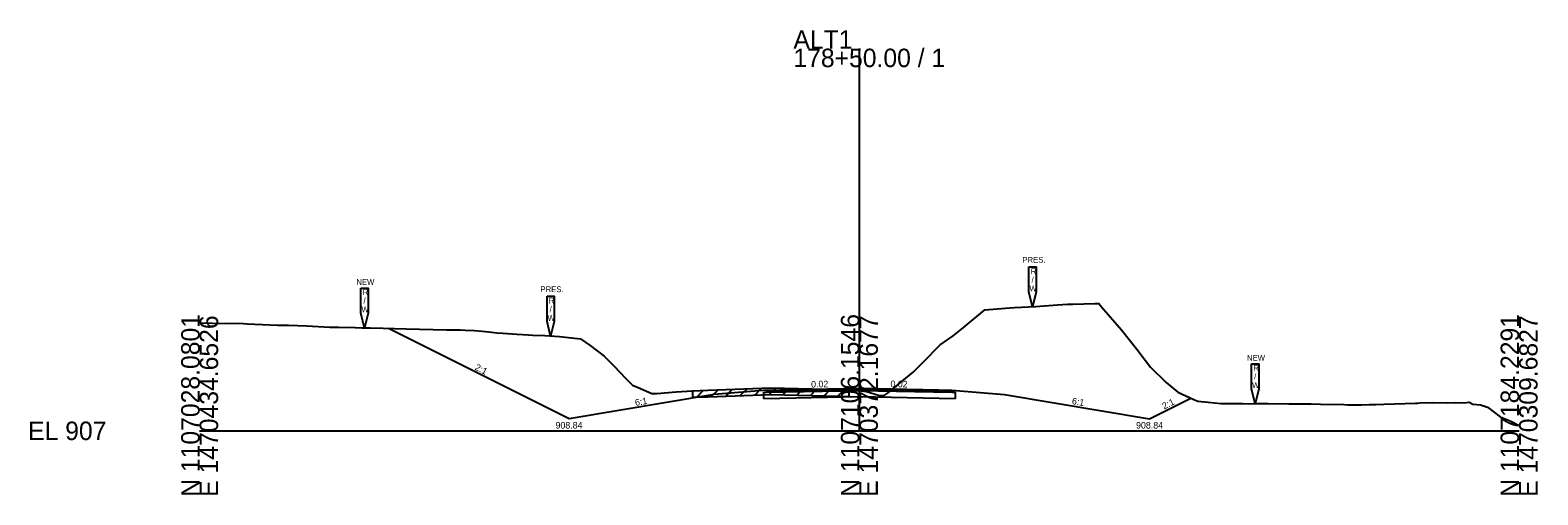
# Model space of a CAD drawing. Extents: x -26 to 2203, y -10 to 19568.
# Drawn here: x 1974.3 to 2202.8, y 490.3 to 560.7 of the extents above; entities that cross this region are included whole.
import ezdxf

# ---------------------------------------------------------------- set-up
doc = ezdxf.new("R2010")
doc.units = 0
for name, color, linetype in [('RD_GPK_XS_Cell', 7, 'Continuous'), ('RD_XS_Base', 7, 'Continuous'), ('RD_XS_ExGround', 7, 'Continuous'), ('RD_XS_ExPaveRet', 7, 'Continuous'), ('RD_XS_ExRW', 7, 'Continuous'), ('RD_XS_Greenside', 7, 'Continuous'), ('RD_XS_NewRW', 7, 'Continuous'), ('RD_XS_Pave', 7, 'Continuous'), ('RD_XS_TieSlope', 7, 'Continuous'), ('RD_XS_TX_Slope', 7, 'Continuous')]:
    doc.layers.add(name, color=color, linetype=linetype)

msp = doc.modelspace()

# ---------------------------------------------------------------- linework, layer by layer
at = {"layer": 'RD_GPK_XS_Cell'}
for p, q in [((2100, 500), (2100, 557.88)), ((2000, 500), (2100, 500)), ((2100, 500), (2200, 500))]:
    msp.add_line(p, q, dxfattribs=at)
at = {"layer": 'RD_XS_Base'}
for points in [[(2085.5, 505.84), (2086, 505.85), (2100, 506.13), (2114, 505.85), (2114.5, 505.84)], [(2085.5, 504.84), (2085.5, 505.84)], [(2114.5, 504.84), (2100, 505.13), (2085.5, 504.84)], [(2114.5, 505.84), (2114.5, 504.84)]]:
    msp.add_lwpolyline(points, dxfattribs=at)
at = {"layer": 'RD_XS_ExGround'}
msp.add_lwpolyline([(2000, 516.34), (2001.94, 516.31), (2006.64, 516.24), (2007.19, 516.22), (2011.84, 516.02), (2013.47, 515.98), (2016.25, 515.91), (2019.75, 515.7), (2021.05, 515.69), (2023.59, 515.65), (2024.6, 515.62), (2025.85, 515.59), (2027.83, 515.54), (2031.28, 515.44), (2037.4, 515.31), (2037.96, 515.28), (2038.96, 515.29), (2039.54, 515.29), (2040.25, 515.25), (2041.67, 515.21), (2042.81, 515.08), (2043.81, 514.98), (2045.06, 514.86), (2045.94, 514.78), (2046.65, 514.74), (2048.07, 514.64), (2049.86, 514.54), (2050.49, 514.51), (2052.34, 514.42), (2054.55, 514.27), (2057.74, 513.91), (2059.19, 512.91), (2061.29, 511.32), (2062.76, 509.85), (2064.53, 507.98), (2065.63, 506.93), (2066.46, 506.55), (2068.55, 505.64), (2068.93, 505.64), (2069.3, 505.64), (2072.23, 505.88), (2074.69, 506.08), (2077.04, 506.17), (2086.57, 506.5), (2094.89, 506.3), (2098.41, 506.21), (2100.23, 506.04), (2101.1, 505.98), (2103.04, 505.33), (2103.78, 505.34), (2104.34, 505.75), (2106.5, 507.52), (2108.13, 508.89), (2109.97, 510.69), (2111.97, 512.78), (2112.27, 513.04), (2114.24, 514.38), (2115.73, 515.59), (2119, 518.34), (2122.17, 518.58), (2122.78, 518.63), (2123.5, 518.67), (2126.67, 518.85), (2127.34, 518.9), (2130.01, 519.07), (2131.54, 519.19), (2132.33, 519.19), (2135.71, 519.29), (2136.27, 519.27), (2136.71, 518.76), (2139.73, 515.32), (2142.07, 512.35), (2144.12, 509.63), (2146.52, 507.33), (2148.28, 505.85), (2150.71, 504.75), (2151.3, 504.49), (2152.85, 504.34), (2154.79, 504.14), (2155.48, 504.14), (2156.92, 504.13), (2158.08, 504.12), (2159.06, 504.11), (2160.28, 504.12), (2161.92, 504.13), (2165.08, 504.09), (2165.46, 504.09), (2165.76, 504.09), (2168.49, 504.07), (2169.89, 504.06), (2173.45, 503.97), (2174, 503.95), (2174.69, 503.96), (2176.13, 503.96), (2177.29, 503.99), (2178.27, 504.01), (2179.49, 504.05), (2181.13, 504.1), (2184.29, 504.19), (2184.67, 504.21), (2184.98, 504.24), (2186.81, 504.29), (2189.17, 504.26), (2190.36, 504.27), (2191.69, 504.24), (2192.41, 504.33), (2193.01, 504.04), (2194.14, 503.94), (2195.19, 503.57), (2196.27, 502.8), (2197.13, 502.11), (2198.39, 501.59), (2198.84, 501.43), (2200, 500.82)], dxfattribs=at)
at = {"layer": 'RD_XS_ExPaveRet'}
for p, q in [((2074.69, 506.08), (2074.69, 505.08)), ((2075.34, 505.1), (2076.38, 506.14)), ((2077.55, 505.19), (2078.58, 506.22)), ((2079.74, 505.26), (2080.78, 506.3)), ((2081.94, 505.34), (2082.98, 506.37)), ((2084.14, 505.41), (2085.18, 506.45)), ((2086.34, 505.49), (2087.33, 506.48)), ((2088.42, 505.46), (2089.4, 506.43)), ((2090.5, 505.41), (2091.47, 506.38)), ((2092.57, 505.36), (2093.55, 506.34)), ((2094.64, 505.31), (2095.62, 506.29)), ((2096.71, 505.26), (2097.69, 506.23)), ((2098.41, 506.21), (2098.41, 505.21))]:
    msp.add_line(p, q, dxfattribs=at)
msp.add_lwpolyline([(2074.69, 505.08), (2077.08, 505.17), (2086.57, 505.5), (2094.87, 505.31), (2098.41, 505.21)], dxfattribs=at)
at = {"layer": 'RD_XS_ExRW'}
for points in [[(2125.7, 524.83), (2126.8, 524.83), (2126.8, 521.01), (2126.25, 518.82), (2125.7, 521.01)], [(2052.66, 520.37), (2053.75, 520.37), (2053.75, 516.54), (2053.2, 514.35), (2052.66, 516.54)]]:
    msp.add_lwpolyline(points, close=True, dxfattribs=at)
at = {"layer": 'RD_XS_Greenside'}
for points in [[(2078, 505.5), (2056, 501.84)], [(2086, 506.17), (2078, 505.5)], [(2114, 506.17), (2122, 505.5)], [(2122, 505.5), (2144, 501.84)]]:
    msp.add_lwpolyline(points, dxfattribs=at)
at = {"layer": 'RD_XS_NewRW'}
for points in [[(2024.45, 521.63), (2025.55, 521.63), (2025.55, 517.8), (2025, 515.61), (2024.45, 517.8)], [(2159.45, 510.14), (2160.55, 510.14), (2160.55, 506.31), (2160, 504.12), (2159.45, 506.31)]]:
    msp.add_lwpolyline(points, close=True, dxfattribs=at)
at = {"layer": 'RD_XS_Pave'}
for points in [[(2086, 506.17), (2088, 506.21), (2100, 506.45), (2112, 506.21), (2114, 506.17)], [(2086, 506.01), (2100, 506.29), (2114, 506.01)], [(2114, 506.01), (2100, 506.29), (2086, 506.01)], [(2086, 506.01), (2086, 506.17)], [(2114, 505.85), (2100, 506.13), (2086, 505.85)], [(2086, 505.85), (2086, 506.01)], [(2114, 506.17), (2114, 506.01)], [(2114, 506.01), (2114, 505.85)]]:
    msp.add_lwpolyline(points, dxfattribs=at)
at = {"layer": 'RD_XS_TieSlope'}
for points in [[(2056, 501.84), (2028.63, 515.52)], [(2144, 501.84), (2150.25, 504.96)]]:
    msp.add_lwpolyline(points, dxfattribs=at)

# ---------------------------------------------------------------- texts
at = {"layer": 'RD_GPK_XS_Cell'}
for s, p in [('ALT1', (2090, 557.88)), ('178+50.00 / 1', (2090, 555.08)), ('EL 907', (1974, 498.6))]:
    msp.add_text(s, height=2.8, dxfattribs=at).set_placement(p)
for s, p in [('N 1107028.0801', (2000, 490)), ('E 1470434.6526', (2002.8, 490)), ('N 1107106.1546', (2100, 490)), ('E 1470372.1677', (2102.8, 490)), ('N 1107184.2291', (2200, 490)), ('E 1470309.6827', (2202.8, 490))]:
    msp.add_text(s, height=2.8, rotation=90, dxfattribs=at).set_placement(p)
at = {"layer": 'RD_XS_ExRW'}
for s, p in [('PRES.', (2124.71, 525.46)), ('R', (2125.97, 523.74)), ('/', (2126.09, 522.43)), ('PRES.', (2051.66, 521)), ('W', (2125.78, 521.12)), ('R', (2052.92, 519.28)), ('/', (2053.04, 517.97)), ('W', (2052.73, 516.65))]:
    msp.add_text(s, height=0.875, dxfattribs=at).set_placement(p)
at = {"layer": 'RD_XS_NewRW'}
for s, p in [('NEW', (2023.75, 522.11)), ('R', (2024.71, 520.59)), ('W', (2024.53, 517.96)), ('/', (2024.83, 519.28)), ('NEW', (2158.75, 510.62)), ('R', (2159.71, 509.1)), ('W', (2159.53, 506.47)), ('/', (2159.83, 507.79))]:
    msp.add_text(s, height=0.875, dxfattribs=at).set_placement(p)
at = {"layer": 'RD_XS_TX_Slope'}
for s, rotation, p in [('2:1', 333.4349, (2041.63, 509.3)), ('0.02', 1.1458, (2092.69, 506.55)), ('0.02', 358.8542, (2104.7, 506.61)), ('6:1', 9.4642, (2066.07, 503.77)), ('6:1', 350.5358, (2132.16, 504.06)), ('2:1', 26.5651, (2146.21, 503.22))]:
    msp.add_text(s, height=1, rotation=rotation, dxfattribs=at).set_placement(p)
for p in [(2053.94, 500.34), (2141.94, 500.34)]:
    msp.add_text('908.84', height=1, dxfattribs=at).set_placement(p)

doc.saveas('drawing.dxf')
